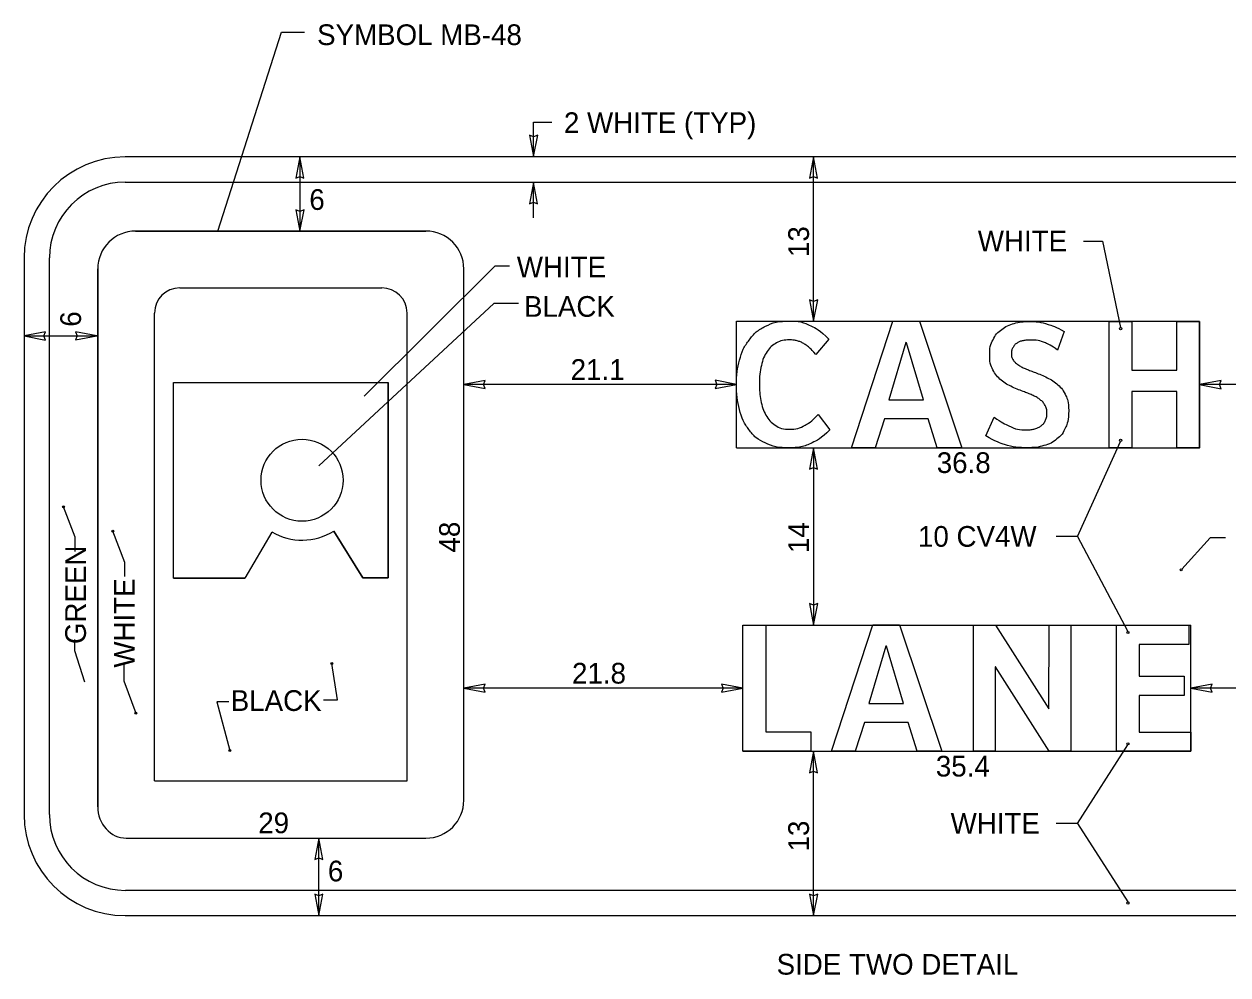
# Model space of a CAD drawing. Extents: x 319706 to 320449, y 1621775 to 1622117.
# Drawn here: x 320155.2 to 320236.5, y 1621847.1 to 1621911.4 of the extents above; entities that cross this region are included whole.
import ezdxf

# ---------------------------------------------------------------- set-up
doc = ezdxf.new("R2010")
doc.units = 0
for name, color, linetype in [('1', 7, 'Continuous'), ('52', 7, 'Continuous'), ('SignPanel', 7, 'Continuous'), ('SOILS_SP83_SHP', 7, 'Continuous')]:
    doc.layers.add(name, color=color, linetype=linetype)

msp = doc.modelspace()

# ---------------------------------------------------------------- linework, layer by layer
at = {"layer": '1'}
for p, q in [((320168.277, 1621897.385), (320172.596, 1621910.821)), ((320172.596, 1621910.821), (320174.144, 1621910.821)), ((320189.623, 1621902.422), (320189.623, 1621904.737)), ((320189.623, 1621904.737), (320190.854, 1621904.737)), ((320189.623, 1621898.276), (320189.623, 1621900.672)), ((320226.773, 1621896.712), (320228.055, 1621896.712)), ((320228.055, 1621896.712), (320229.284, 1621890.861)), ((320186.989, 1621895.012), (320178.163, 1621886.213)), ((320187.98, 1621895.012), (320186.989, 1621895.012)), ((320186.926, 1621892.483), (320175.104, 1621881.525)), ((320188.6, 1621892.483), (320186.926, 1621892.483)), ((320226.378, 1621876.744), (320229.284, 1621883.169)), ((320158.654, 1621876.692), (320157.848, 1621878.743)), ((320158.654, 1621875.734), (320158.654, 1621876.692)), ((320162, 1621874.983), (320161.193, 1621877.102)), ((320226.378, 1621876.744), (320224.936, 1621876.744)), ((320226.378, 1621876.744), (320229.777, 1621870.318)), ((320235.337, 1621876.644), (320233.425, 1621874.53)), ((320236.361, 1621876.644), (320235.337, 1621876.644)), ((320162, 1621874.026), (320162, 1621874.983)), ((320158.592, 1621869.774), (320158.592, 1621869.037)), ((320158.592, 1621869.037), (320159.273, 1621866.916)), ((320161.937, 1621868.078), (320161.937, 1621866.985)), ((320176.358, 1621865.694), (320175.986, 1621868.155)), ((320161.937, 1621866.985), (320162.743, 1621864.798)), ((320169.025, 1621865.556), (320168.22, 1621865.556)), ((320168.22, 1621865.556), (320169.088, 1621862.275)), ((320175.428, 1621865.694), (320176.358, 1621865.694)), ((320226.378, 1621857.34), (320229.777, 1621862.649)), ((320226.378, 1621857.34), (320224.936, 1621857.34)), ((320226.378, 1621857.34), (320229.777, 1621852.03))]:
    msp.add_line(p, q, dxfattribs=at)
for centre, major_axis, ratio in [((320229.284, 1621890.79), (0.0736, 0), 0.960359), ((320229.284, 1621883.24), (0.0736, 0), 0.960359), ((320157.848, 1621878.741), (0, 0.0707), 0.906668), ((320161.194, 1621877.1), (0, 0.0707), 0.906668), ((320233.378, 1621874.482), (0, 0.0707), 0.906668), ((320229.777, 1621870.248), (0.0736, 0), 0.961364), ((320175.986, 1621868.153), (0, 0.0707), 0.906668), ((320162.742, 1621864.796), (0, 0.0707), 0.906668), ((320229.777, 1621862.72), (0.0736, 0), 0.960359), ((320169.087, 1621862.275), (0, 0.0707), 0.906668), ((320229.777, 1621851.96), (0.0736, 0), 0.961364)]:
    msp.add_ellipse(centre, major_axis=major_axis, ratio=ratio, dxfattribs=at)
at = {"layer": '52'}
for p, q in [((320189.623, 1621903.762), (320189.353, 1621903.872)), ((320189.353, 1621903.872), (320189.623, 1621902.422)), ((320189.623, 1621902.422), (320189.903, 1621903.872)), ((320189.903, 1621903.872), (320189.623, 1621903.762)), ((320173.826, 1621902.405), (320173.546, 1621900.955)), ((320174.096, 1621900.955), (320173.826, 1621902.405)), ((320208.536, 1621902.405), (320208.256, 1621900.955)), ((320208.806, 1621900.955), (320208.536, 1621902.405)), ((320173.546, 1621900.955), (320173.826, 1621901.065)), ((320173.826, 1621901.065), (320174.096, 1621900.955)), ((320208.256, 1621900.955), (320208.536, 1621901.065)), ((320208.536, 1621901.065), (320208.806, 1621900.955)), ((320189.623, 1621900.672), (320189.343, 1621899.222)), ((320189.893, 1621899.222), (320189.623, 1621900.672)), ((320189.343, 1621899.222), (320189.623, 1621899.332)), ((320189.623, 1621899.332), (320189.893, 1621899.222)), ((320173.826, 1621898.712), (320173.556, 1621898.822)), ((320173.556, 1621898.822), (320173.826, 1621897.372)), ((320173.826, 1621897.372), (320174.106, 1621898.822)), ((320174.106, 1621898.822), (320173.826, 1621898.712)), ((320208.536, 1621892.63), (320208.266, 1621892.74)), ((320208.266, 1621892.74), (320208.536, 1621891.29)), ((320208.536, 1621891.29), (320208.816, 1621892.74)), ((320208.816, 1621892.74), (320208.536, 1621892.63)), ((320156.641, 1621890.569), (320155.191, 1621890.299)), ((320156.531, 1621890.299), (320156.641, 1621890.569)), ((320160.108, 1621890.299), (320158.658, 1621890.579)), ((320158.658, 1621890.579), (320158.768, 1621890.299)), ((320155.191, 1621890.299), (320156.641, 1621890.019)), ((320156.641, 1621890.019), (320156.531, 1621890.299)), ((320158.768, 1621890.299), (320158.658, 1621890.029)), ((320158.658, 1621890.029), (320160.108, 1621890.299)), ((320186.353, 1621887.285), (320184.903, 1621887.015)), ((320186.243, 1621887.015), (320186.353, 1621887.285)), ((320203.332, 1621887.015), (320201.882, 1621887.295)), ((320201.882, 1621887.295), (320201.992, 1621887.015)), ((320236.071, 1621887.274), (320234.621, 1621887.004)), ((320235.961, 1621887.004), (320236.071, 1621887.274)), ((320184.903, 1621887.015), (320186.353, 1621886.735)), ((320186.353, 1621886.735), (320186.243, 1621887.015)), ((320201.992, 1621887.015), (320201.882, 1621886.745)), ((320201.882, 1621886.745), (320203.332, 1621887.015)), ((320234.621, 1621887.004), (320236.071, 1621886.724)), ((320236.071, 1621886.724), (320235.961, 1621887.004)), ((320208.536, 1621882.74), (320208.256, 1621881.29)), ((320208.806, 1621881.29), (320208.536, 1621882.74)), ((320208.256, 1621881.29), (320208.536, 1621881.4)), ((320208.536, 1621881.4), (320208.806, 1621881.29)), ((320208.536, 1621872.088), (320208.266, 1621872.198)), ((320208.266, 1621872.198), (320208.536, 1621870.748)), ((320208.536, 1621870.748), (320208.816, 1621872.198)), ((320208.816, 1621872.198), (320208.536, 1621872.088)), ((320186.353, 1621866.754), (320184.903, 1621866.484)), ((320184.903, 1621866.484), (320186.353, 1621866.204)), ((320186.243, 1621866.484), (320186.353, 1621866.754)), ((320186.353, 1621866.204), (320186.243, 1621866.484)), ((320203.763, 1621866.484), (320202.313, 1621866.764)), ((320202.313, 1621866.764), (320202.423, 1621866.484)), ((320202.423, 1621866.484), (320202.313, 1621866.214)), ((320202.313, 1621866.214), (320203.763, 1621866.484)), ((320235.471, 1621866.754), (320234.021, 1621866.484)), ((320234.021, 1621866.484), (320235.471, 1621866.204)), ((320235.361, 1621866.484), (320235.471, 1621866.754)), ((320235.471, 1621866.204), (320235.361, 1621866.484)), ((320208.536, 1621862.22), (320208.256, 1621860.77)), ((320208.806, 1621860.77), (320208.536, 1621862.22)), ((320208.256, 1621860.77), (320208.536, 1621860.88)), ((320208.536, 1621860.88), (320208.806, 1621860.77)), ((320175.109, 1621856.351), (320174.829, 1621854.901)), ((320175.379, 1621854.901), (320175.109, 1621856.351)), ((320174.829, 1621854.901), (320175.109, 1621855.011)), ((320175.109, 1621855.011), (320175.379, 1621854.901)), ((320175.109, 1621852.445), (320174.839, 1621852.555)), ((320174.839, 1621852.555), (320175.109, 1621851.105)), ((320175.109, 1621851.105), (320175.389, 1621852.555)), ((320175.389, 1621852.555), (320175.109, 1621852.445)), ((320208.536, 1621852.445), (320208.266, 1621852.555)), ((320208.266, 1621852.555), (320208.536, 1621851.105)), ((320208.536, 1621851.105), (320208.816, 1621852.555)), ((320208.816, 1621852.555), (320208.536, 1621852.445))]:
    msp.add_line(p, q, dxfattribs=at)
at = {"layer": 'SignPanel'}
for p, q in [((320271.472, 1621902.405), (320162.031, 1621902.405)), ((320173.826, 1621902.405), (320173.826, 1621897.372)), ((320208.536, 1621891.29), (320208.536, 1621902.405)), ((320162.031, 1621900.695), (320271.472, 1621900.695)), ((320162.729, 1621897.382), (320182.346, 1621897.382)), ((320182.346, 1621897.382), (320162.729, 1621897.382)), ((320155.191, 1621895.565), (320155.191, 1621857.945)), ((320156.901, 1621857.945), (320156.901, 1621895.565)), ((320160.169, 1621858.465), (320160.169, 1621894.826)), ((320160.169, 1621894.826), (320160.169, 1621858.465)), ((320184.903, 1621858.907), (320184.903, 1621894.826)), ((320184.903, 1621858.907), (320184.903, 1621894.826)), ((320165.713, 1621893.546), (320165.713, 1621893.544)), ((320165.713, 1621893.544), (320179.36, 1621893.544)), ((320164.007, 1621860.228), (320164.007, 1621891.838)), ((320181.066, 1621860.228), (320181.066, 1621891.838)), ((320155.191, 1621890.299), (320160.108, 1621890.299)), ((320165.288, 1621873.928), (320165.288, 1621887.148)), ((320165.288, 1621887.148), (320179.786, 1621887.148)), ((320165.288, 1621873.928), (320165.288, 1621887.148)), ((320165.288, 1621887.148), (320179.786, 1621887.148)), ((320179.786, 1621873.94), (320179.786, 1621887.148)), ((320179.786, 1621887.148), (320179.786, 1621873.94)), ((320203.332, 1621887.015), (320184.903, 1621887.015)), ((320252.662, 1621887.004), (320234.621, 1621887.004)), ((320208.536, 1621882.74), (320208.536, 1621870.748)), ((320171.929, 1621877.04), (320170.112, 1621873.928)), ((320171.929, 1621877.04), (320170.112, 1621873.928)), ((320176.113, 1621877.098), (320178.081, 1621873.94)), ((320178.081, 1621873.94), (320176.113, 1621877.098)), ((320165.288, 1621873.928), (320170.112, 1621873.928)), ((320170.112, 1621873.928), (320165.288, 1621873.928)), ((320178.081, 1621873.94), (320179.786, 1621873.94)), ((320179.786, 1621873.94), (320178.081, 1621873.94)), ((320203.763, 1621866.484), (320184.903, 1621866.484)), ((320252.673, 1621866.484), (320234.021, 1621866.484)), ((320208.536, 1621851.105), (320208.536, 1621862.22)), ((320164.007, 1621860.228), (320181.066, 1621860.228)), ((320162.088, 1621856.349), (320162.088, 1621856.347)), ((320162.088, 1621856.347), (320182.346, 1621856.347)), ((320162.088, 1621856.347), (320182.346, 1621856.347)), ((320175.109, 1621851.105), (320175.109, 1621856.351)), ((320271.472, 1621852.815), (320162.048, 1621852.815)), ((320162.048, 1621851.105), (320271.472, 1621851.105))]:
    msp.add_line(p, q, dxfattribs=at)
for points in [[(320216.897, 1621882.74), (320216.275, 1621884.689), (320213.325, 1621884.689), (320212.702, 1621882.74), (320211.099, 1621882.74), (320213.896, 1621891.29), (320215.695, 1621891.29), (320218.551, 1621882.74), (320216.897, 1621882.74)], [(320233.09, 1621882.74), (320233.09, 1621886.535), (320230.05, 1621886.535), (320230.05, 1621882.74), (320228.518, 1621882.74), (320228.518, 1621891.268), (320230.05, 1621891.268), (320230.05, 1621887.971), (320233.09, 1621887.971), (320233.09, 1621891.268), (320234.621, 1621891.268), (320234.621, 1621882.74), (320233.09, 1621882.74)], [(320225.471, 1621890.597), (320225.031, 1621889.344)], [(320209.571, 1621890.074), (320208.686, 1621889.047)], [(320214.817, 1621889.839), (320214.774, 1621889.841), (320213.631, 1621885.971), (320215.959, 1621885.971), (320214.817, 1621889.839)], [(320208.84, 1621884.984), (320209.635, 1621883.949)], [(320220.185, 1621883.553), (320220.75, 1621884.797)], [(320203.763, 1621862.22), (320203.763, 1621870.748), (320205.309, 1621870.748), (320205.309, 1621863.524), (320208.357, 1621863.524), (320208.357, 1621862.22), (320203.763, 1621862.22)], [(320215.543, 1621862.22), (320214.921, 1621864.169), (320211.971, 1621864.169), (320211.349, 1621862.22), (320209.746, 1621862.22), (320212.542, 1621870.77), (320214.341, 1621870.77), (320217.197, 1621862.22), (320215.543, 1621862.22)], [(320224.449, 1621862.22), (320220.837, 1621867.933), (320220.815, 1621867.933), (320220.815, 1621862.22), (320219.35, 1621862.22), (320219.35, 1621870.748), (320220.837, 1621870.748), (320224.435, 1621865.094), (320224.445, 1621865.094), (320224.449, 1621870.748), (320225.922, 1621870.748), (320225.922, 1621862.22), (320224.449, 1621862.22)], [(320229.012, 1621862.22), (320229.012, 1621870.748), (320233.898, 1621870.748), (320233.898, 1621869.444), (320230.543, 1621869.444), (320230.543, 1621867.297), (320233.576, 1621867.297), (320233.576, 1621865.985), (320230.543, 1621865.985), (320230.543, 1621863.502), (320234.021, 1621863.502), (320234.021, 1621862.22), (320229.012, 1621862.22)], [(320213.463, 1621869.319), (320213.42, 1621869.321), (320212.278, 1621865.451), (320214.605, 1621865.451), (320213.463, 1621869.319)]]:
    msp.add_lwpolyline(points, dxfattribs=at)
msp.add_circle((320173.972, 1621880.54), 2.772, dxfattribs=at)
for centre, radius, start, end in [((320162.031, 1621895.565), 6.84, 90, 180), ((320162.031, 1621895.565), 5.13, 90, 180), ((320162.728, 1621894.826), 2.559, 90, 180), ((320162.728, 1621894.826), 2.559, 90, 180), ((320182.345, 1621894.826), 2.559, 0, 90), ((320182.345, 1621894.826), 2.559, 0, 90), ((320165.713, 1621891.841), 1.706, 90, 180), ((320179.36, 1621891.841), 1.706, 0, 90), ((320173.972, 1621880.54), 4.051, 239.72059, 301.90487), ((320173.972, 1621880.54), 4.051, 239.72059, 301.90487), ((320182.345, 1621858.907), 2.559, 270, 360), ((320182.345, 1621858.907), 2.559, 270, 360), ((320162.031, 1621857.945), 6.84, 180, 270), ((320162.031, 1621857.945), 5.13, 180, 270)]:
    msp.add_arc(centre, radius, start, end, dxfattribs=at)
msp.add_ellipse((320162.088, 1621858.466), major_axis=(0, 2.117), ratio=0.906668, start_param=1.570796, end_param=3.141593, dxfattribs=at)
msp.add_ellipse((320162.088, 1621858.466), major_axis=(0, 2.117), ratio=0.906668, start_param=1.570796, end_param=3.141593, dxfattribs=at)
for points in [[(320209.635, 1621883.949), (320209.064, 1621883.369), (320208.388, 1621883.054), (320207.713, 1621882.739), (320206.885, 1621882.739), (320205.949, 1621882.739), (320205.278, 1621883.062), (320204.607, 1621883.385), (320204.173, 1621883.96), (320203.738, 1621884.536), (320203.535, 1621885.322), (320203.332, 1621886.108), (320203.332, 1621887.035), (320203.332, 1621887.896), (320203.543, 1621888.666), (320203.754, 1621889.436), (320204.188, 1621890.02), (320204.623, 1621890.603), (320205.293, 1621890.947), (320205.963, 1621891.29), (320206.89, 1621891.29), (320207.701, 1621891.29), (320208.334, 1621890.988), (320208.967, 1621890.686), (320209.571, 1621890.074)], [(320220.75, 1621884.797), (320221.231, 1621884.442), (320221.766, 1621884.193), (320222.302, 1621883.945), (320222.916, 1621883.945), (320223.181, 1621883.945), (320223.43, 1621884.003), (320223.679, 1621884.061), (320223.874, 1621884.194), (320224.069, 1621884.326), (320224.185, 1621884.546), (320224.301, 1621884.766), (320224.301, 1621885.097), (320224.301, 1621885.387), (320224.181, 1621885.603), (320224.06, 1621885.819), (320223.853, 1621885.98), (320223.646, 1621886.142), (320223.376, 1621886.266), (320223.106, 1621886.391), (320222.799, 1621886.498), (320222.393, 1621886.656), (320221.974, 1621886.843), (320221.555, 1621887.029), (320221.214, 1621887.311), (320220.874, 1621887.594), (320220.659, 1621888.004), (320220.443, 1621888.415), (320220.443, 1621889.021), (320220.443, 1621889.618), (320220.663, 1621890.041), (320220.883, 1621890.464), (320221.252, 1621890.738), (320221.621, 1621891.012), (320222.094, 1621891.141), (320222.567, 1621891.269), (320223.073, 1621891.269), (320223.745, 1621891.269), (320224.33, 1621891.091), (320224.915, 1621890.913), (320225.471, 1621890.597)], [(320208.686, 1621889.047), (320208.48, 1621889.287), (320208.281, 1621889.469), (320208.083, 1621889.652), (320207.872, 1621889.776), (320207.661, 1621889.9), (320207.429, 1621889.962), (320207.198, 1621890.024), (320206.925, 1621890.024), (320206.412, 1621890.024), (320206.032, 1621889.821), (320205.652, 1621889.618), (320205.395, 1621889.234), (320205.139, 1621888.849), (320205.011, 1621888.294), (320204.883, 1621887.74), (320204.883, 1621887.036), (320204.883, 1621886.465), (320204.982, 1621885.923), (320205.082, 1621885.381), (320205.317, 1621884.95), (320205.553, 1621884.52), (320205.947, 1621884.259), (320206.34, 1621883.998), (320206.928, 1621883.998), (320207.491, 1621883.998), (320207.934, 1621884.243), (320208.377, 1621884.487), (320208.84, 1621884.984)], [(320225.031, 1621889.344), (320224.6, 1621889.658), (320224.164, 1621889.84), (320223.729, 1621890.021), (320223.181, 1621890.021), (320222.924, 1621890.021), (320222.696, 1621889.976), (320222.468, 1621889.93), (320222.294, 1621889.818), (320222.119, 1621889.706), (320222.016, 1621889.524), (320221.912, 1621889.342), (320221.912, 1621889.077), (320221.912, 1621888.828), (320222.045, 1621888.646), (320222.177, 1621888.464), (320222.401, 1621888.319), (320222.625, 1621888.174), (320222.916, 1621888.058), (320223.206, 1621887.942), (320223.521, 1621887.818), (320223.919, 1621887.668), (320224.322, 1621887.473), (320224.724, 1621887.278), (320225.047, 1621886.988), (320225.371, 1621886.698), (320225.574, 1621886.274), (320225.777, 1621885.851), (320225.777, 1621885.246)], [(320225.777, 1621885.246), (320225.777, 1621884.582), (320225.566, 1621884.109), (320225.354, 1621883.636), (320224.981, 1621883.329), (320224.608, 1621883.022), (320224.097, 1621882.881), (320223.587, 1621882.74), (320222.99, 1621882.74), (320222.177, 1621882.74), (320221.505, 1621882.939), (320220.833, 1621883.138), (320220.185, 1621883.553)]]:
    msp.add_open_spline(points, degree=3, dxfattribs=at)
at = {"layer": 'SOILS_SP83_SHP'}
for p, q in [((320203.332, 1621891.29), (320234.621, 1621891.29)), ((320203.332, 1621882.74), (320203.332, 1621891.29)), ((320234.621, 1621882.707), (320234.621, 1621891.194)), ((320203.332, 1621882.74), (320234.621, 1621882.74)), ((320203.763, 1621870.748), (320234.021, 1621870.748)), ((320203.763, 1621862.22), (320203.763, 1621870.708)), ((320234.021, 1621862.22), (320234.021, 1621870.748)), ((320203.763, 1621862.22), (320234.021, 1621862.22))]:
    msp.add_line(p, q, dxfattribs=at)

# ---------------------------------------------------------------- texts
at = {"layer": '1'}
for s, p in [('SYMBOL MB-48', (320174.989, 1621909.958)), ('2 WHITE (TYP)', (320191.669, 1621904.012)), ('WHITE', (320219.637, 1621896.012)), ('WHITE', (320188.487, 1621894.25)), ('BLACK', (320188.972, 1621891.589)), ('21.1', (320192.124, 1621887.326)), ('36.8', (320216.861, 1621881.03)), ('10 CV4W', (320215.594, 1621876.044)), ('21.8', (320192.217, 1621866.794)), ('BLACK', (320169.155, 1621864.945)), ('35.4', (320216.8, 1621860.51)), ('29', (320171.016, 1621856.679)), ('WHITE', (320217.8, 1621856.64)), ('SIDE TWO DETAIL', (320206.041, 1621847.118))]:
    msp.add_text(s, height=1.4, dxfattribs=at).set_placement(p)
for s, p in [('13', (320208.226, 1621895.631)), ('48', (320184.638, 1621875.655)), ('14', (320208.226, 1621875.614)), ('GREEN', (320159.371, 1621869.466)), ('WHITE', (320162.671, 1621867.872)), ('13', (320208.226, 1621855.446))]:
    msp.add_text(s, height=1.4, rotation=90, dxfattribs=at).set_placement(p)
at = {"layer": 'SignPanel'}
for p in [(320174.465, 1621898.816), (320175.72, 1621853.423)]:
    msp.add_text('6', height=1.4, dxfattribs=at).set_placement(p)
msp.add_text('6', height=1.4, rotation=90, dxfattribs=at).set_placement((320159.039, 1621890.918))

doc.saveas('drawing.dxf')
